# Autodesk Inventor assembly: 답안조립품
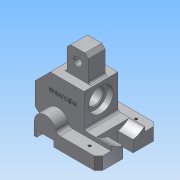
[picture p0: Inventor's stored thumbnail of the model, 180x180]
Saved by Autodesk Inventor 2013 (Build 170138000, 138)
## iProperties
Created: 2016-11
Part Number: 답안조립품
Document SubType Name: Assembly
Designer: Administrator
Author: Administrator
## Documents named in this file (2)
- C:\Users\Administrator\Desktop\461108V1030\답안조립품.iam
- C:\Users\Administrator\Desktop\461108V1030\본체.ipt
